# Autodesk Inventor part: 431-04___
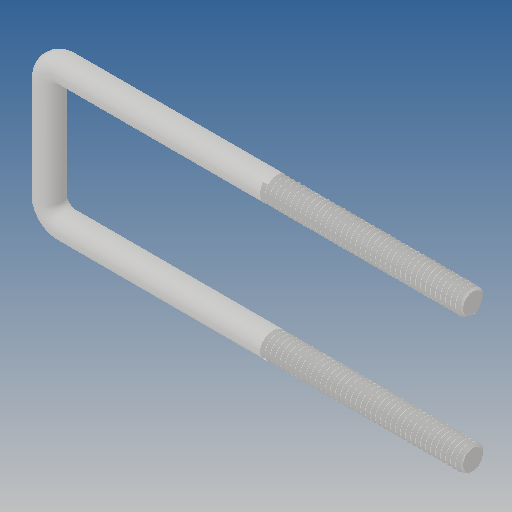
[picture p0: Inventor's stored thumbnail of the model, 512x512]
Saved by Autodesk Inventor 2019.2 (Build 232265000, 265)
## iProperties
Created: 2010-06
Part Number: 431-04___
Material: Ogólny
Document SubType Name: Modeling
Designer: CADENGINEERING4
Density: 1 g/cm^3
Appearance: Domyślna
Author: CADENGINEERING4
Revision Number: ANY
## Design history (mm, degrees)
feature "NONE"
node "Bryła1"
